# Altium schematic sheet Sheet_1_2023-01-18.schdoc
size 135 x 118 mm
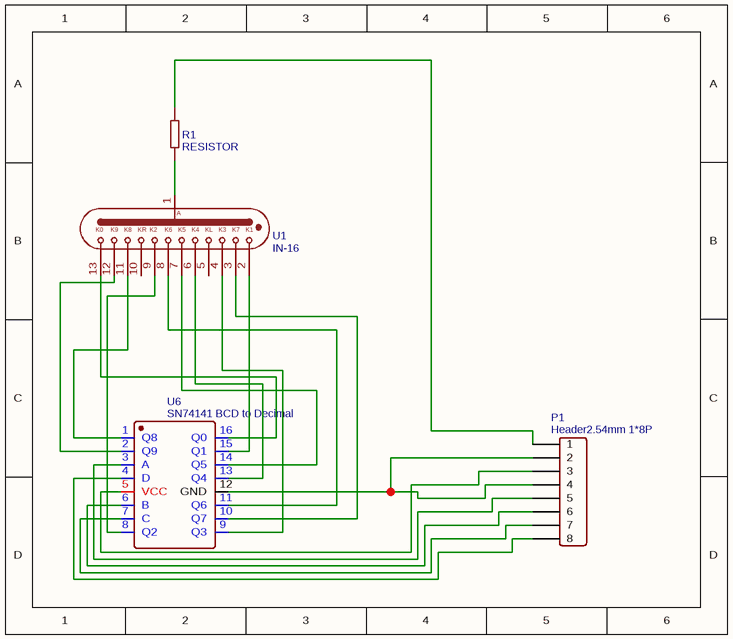
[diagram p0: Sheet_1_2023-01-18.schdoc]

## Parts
P1  Header2.54mm 1*8P  [HDR-8X1/2.54]
R1  RESISTOR  [RTH025W]
U1  IN-16  [IN-16 FOOTPRINT]
U6  SN74141 BCD to Decimal  [DIP16]

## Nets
NetP1_1: P1.1 R1.2
NetP1_2: P1.2 P1.4 U6.12(GND)
NetP1_3: P1.3 U6.5(VCC)
NetP1_5: P1.5 U6.3(A)
NetP1_6: P1.6 U6.6(B)
NetP1_7: P1.7 U6.7(C)
NetP1_8: P1.8 U6.4(D)
NetR1_1: R1.1 U1.1
NetU1_2: U1.2 U6.15(Q1)
NetU1_3: U1.3 U6.10(Q7)
NetU1_4: U1.4 U6.9(Q3)
NetU1_6: U1.6 U6.13(Q4)
NetU1_7: U1.7 U6.14(Q5)
NetU1_8: U1.8 U6.11(Q6)
NetU1_9: U1.9 U6.8(Q2)
NetU1_11: U1.11 U6.1(Q8)
NetU1_12: U1.12 U6.2(Q9)
NetU1_13: U1.13 U6.16(Q0)

Not connected (* = marked no-connect by the designer): U1 5 10

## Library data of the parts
P1 = Header2.54mm 1*8P: BOM_Manufacturer: ReliaPro
R1 = RESISTOR: Contributor: DangerousPrototype; BOM_VALUE: 20K
U1 = IN-16: BOM_Manufacturer Part: IN-14; Contributor: AndySmithersHome
U6 = SN74141 BCD to Decimal: Contributor: David Hovannesian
